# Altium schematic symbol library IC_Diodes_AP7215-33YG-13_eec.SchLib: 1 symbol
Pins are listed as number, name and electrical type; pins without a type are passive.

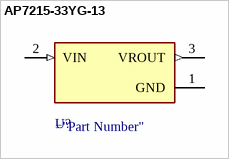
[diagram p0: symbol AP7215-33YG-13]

## AP7215-33YG-13
designator U?  (value not drawn)
pins: 1 GND (power), 2 VIN (in), 3 VROUT (out)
